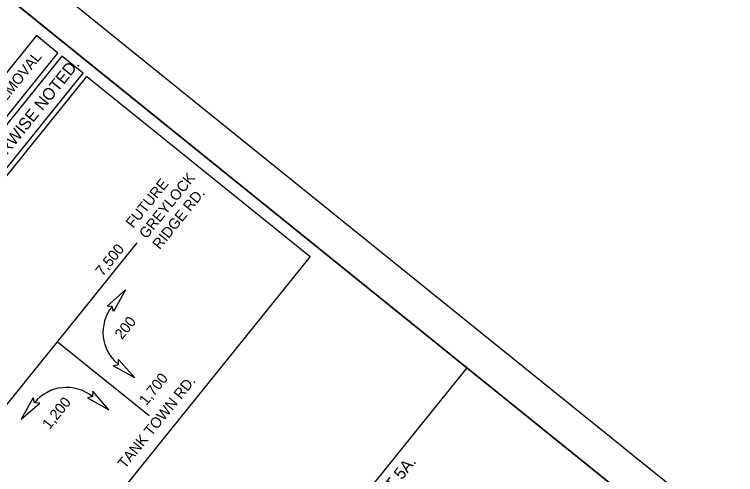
# Model space of a CAD drawing. Extents: x 1487832 to 1490056, y 498345 to 500343.
# Drawn here: x 1489387.8 to 1489727.7, y 499731.4 to 499948.3 of the extents above; entities that cross this region are included whole.
import ezdxf

# ---------------------------------------------------------------- set-up
doc = ezdxf.new("R2010")
doc.units = 0
for name, color, linetype in [('Prop DSN Text', 7, 'Continuous'), ('Prop Grid Mask', 7, 'Continuous'), ('Prop Horizontal Alignment Curve and Spiral Data', 7, 'Continuous'), ('Sheet Clip Boundary CELL', 7, 'Continuous'), ('Sheet Plan CELL', 7, 'Continuous'), ('Sheet Plot Border Outside CELL', 7, 'Continuous')]:
    doc.layers.add(name, color=color, linetype=linetype)

msp = doc.modelspace()

# ---------------------------------------------------------------- linework, layer by layer
at = {"layer": 'Prop DSN Text'}
for p, q in [((1489445.44, 499840.58), (1489407.93, 499794.07)), ((1489407.93, 499794.07), (1489370.43, 499747.57)), ((1489451.26, 499759.13), (1489407.93, 499794.07))]:
    msp.add_line(p, q, dxfattribs=at)
for points in [[(1489431.41, 499810.82), (1489440.09, 499818.46), (1489434.47, 499808.27), (1489433.81, 499810.67)], [(1489436.89, 499785.73), (1489444.53, 499777.05), (1489434.34, 499782.67), (1489436.74, 499783.33)], [(1489422.22, 499767.54), (1489432.32, 499761.92), (1489424.67, 499770.69), (1489424.54, 499768.2)], [(1489396.54, 499767.58), (1489390.92, 499757.48), (1489399.68, 499765.13), (1489397.19, 499765.27)]]:
    msp.add_lwpolyline(points, close=True, dxfattribs=at)
for centre, start, end in [((1489448.95, 499798.47), 141.1156, 231.1156), ((1489412.33, 499753.06), 51.1156, 141.1156)]:
    msp.add_arc(centre, 19.44, start, end, dxfattribs=at)
at = {"layer": 'Prop Grid Mask'}
for points in [[(1489328, 499830.53), (1489408.29, 499930.09), (1489398.12, 499938.29), (1489317.83, 499838.73)], [(1489269.83, 499734.17), (1489420.13, 499920.54), (1489410.09, 499928.63), (1489259.79, 499742.26)], [(1489252.37, 499708.83), (1489421.93, 499919.09), (1489527.15, 499834.24), (1489357.58, 499623.98)], [(1489502.46, 499445.87), (1489705.45, 499697.58), (1489601.09, 499781.75), (1489398.1, 499530.03)]]:
    msp.add_lwpolyline(points, close=True, dxfattribs=at)
at = {"layer": 'Sheet Clip Boundary CELL'}
msp.add_lwpolyline([(1488948.36, 500051.16), (1488813.25, 500160.1), (1488087.84, 499260.53), (1488879.09, 498569.08), (1489756.18, 499656.68), (1489073.94, 500206.87)], close=True, dxfattribs=at)
at = {"layer": 'Sheet Plan CELL'}
for points in [[(1488938.86, 500315.83), (1487997.21, 499148.18), (1488814.55, 498489.05), (1489756.18, 499656.68)], [(1488814.55, 498489.05), (1487997.21, 499148.15), (1488813.25, 500160.1), (1488930.07, 500065.91), (1489055.66, 500221.61), (1489756.18, 499656.68)]]:
    msp.add_lwpolyline(points, close=True, dxfattribs=at)
at = {"layer": 'Sheet Plot Border Outside CELL'}
msp.add_lwpolyline([(1488727.56, 498345.32), (1489784.38, 499655.78), (1488932.01, 500343.17), (1487875.19, 499032.7)], close=True, dxfattribs=at)

# ---------------------------------------------------------------- texts
at = {"layer": 'Prop DSN Text'}
for s, rotation, p in [('PAVEMENT REMOVAL', 51.1157, (1489356.12, 499872.76)), ('GREYLOCK', 51.1156, (1489449.97, 499842.21)), ('FUTURE', 51.1156, (1489443.71, 499847.25)), ('RIDGE RD.', 51.1156, (1489456.22, 499837.16)), ('7,500', 51.1156, (1489429.36, 499824.57)), ('200', 51.1156, (1489438.44, 499794.74)), ('1,700', 51.1156, (1489449.95, 499763.71)), ('TANK TOWN RD.', 51.1156, (1489439.92, 499733.87)), ('1,200', 51.1156, (1489404.28, 499752.39))]:
    msp.add_text(s, height=5, rotation=rotation, dxfattribs=at).set_placement(p)
at = {"layer": 'Prop Horizontal Alignment Curve and Spiral Data'}
for s, p in [('NOTE:  ALL DRIVEWAY RADII 10 FT UNLESS OTHERWISE NOTED.', (1489270.06, 499740.24)), ('FOR ADDITIONAL ROW & EASEMENT INFORMATION SEE SHEET 5A.', (1489422.72, 499545.5))]:
    msp.add_text(s, height=5.625, rotation=51.1156, dxfattribs=at).set_placement(p)

doc.saveas('drawing.dxf')
